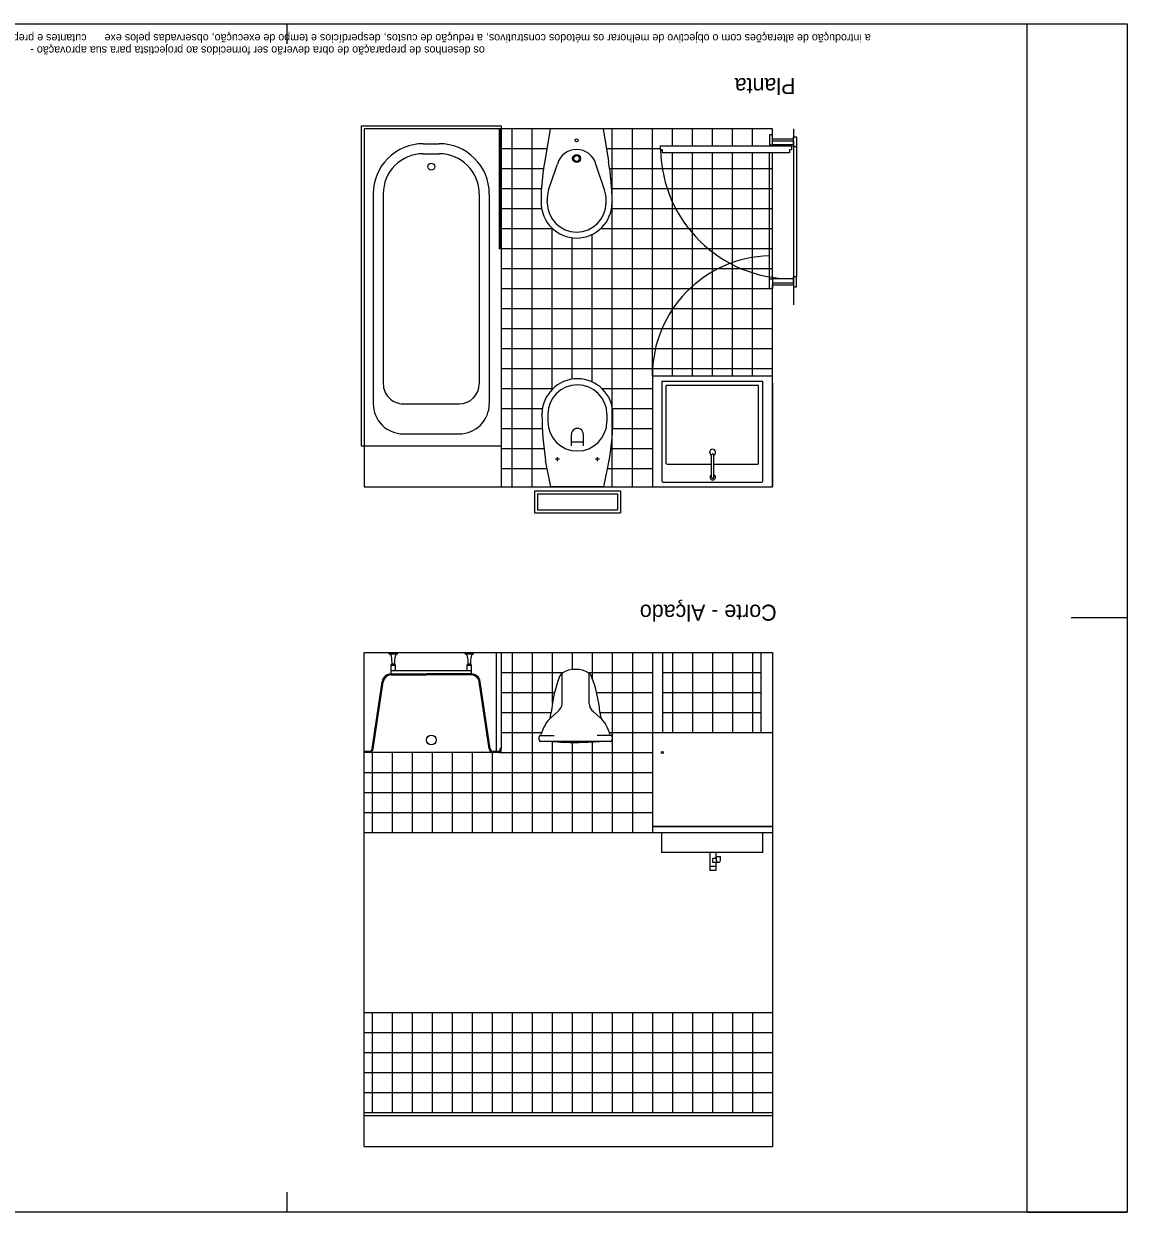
# Model space of a CAD drawing. Extents: x 1279.2 to 1290.8, y -284.8 to -278.9.
# Drawn here: x 1285.25 to 1290.76, y -284.82 to -278.88 of the extents above; entities that cross this region are included whole.
import ezdxf

# ---------------------------------------------------------------- set-up
doc = ezdxf.new("R2010")
doc.units = 0
for name, color, linetype in [('Level 1', 7, 'Continuous'), ('Level 10', 7, 'Continuous'), ('Level 11', 7, 'Continuous'), ('Level 13', 7, 'Continuous'), ('Level 18', 7, 'Continuous'), ('Level 2', 7, 'Continuous'), ('Level 36', 7, 'Continuous'), ('Level 4', 7, 'Continuous'), ('Level 60', 7, 'Continuous'), ('Level 62', 7, 'Continuous')]:
    doc.layers.add(name, color=color, linetype=linetype)

msp = doc.modelspace()

# ---------------------------------------------------------------- linework, layer by layer
at = {"layer": 'Level 1'}
for p, q in [((1288.9899, -279.4078), (1286.9499, -279.4078)), ((1286.9499, -279.4078), (1286.9499, -281.1978)), ((1288.9899, -279.4578), (1288.9899, -279.4078)), ((1289.0949, -279.4078), (1289.0949, -279.4578)), ((1288.9899, -279.4578), (1289.0949, -279.4578)), ((1288.9899, -281.1978), (1288.9899, -280.1878)), ((1288.9899, -280.1878), (1289.0949, -280.1878)), ((1289.0949, -280.1878), (1289.0949, -280.2878)), ((1286.9499, -281.1978), (1288.9899, -281.1978)), ((1286.9499, -282.0252), (1288.9899, -282.0252)), ((1286.9499, -284.4952), (1286.9499, -282.0252)), ((1287.6099, -282.0252), (1287.6099, -282.5202)), ((1287.6349, -282.0252), (1287.6349, -282.5052)), ((1288.9899, -282.0252), (1288.9899, -284.4952)), ((1287.6349, -282.5052), (1287.6299, -282.5052)), ((1287.6299, -282.5052), (1287.6299, -282.5102)), ((1287.6199, -282.5202), (1287.6099, -282.5202)), ((1286.9499, -284.3252), (1287.6349, -284.3252)), ((1286.9499, -284.3402), (1288.9899, -284.3402)), ((1287.6349, -284.3252), (1288.9899, -284.3252)), ((1286.9499, -284.4952), (1288.9899, -284.4952))]:
    msp.add_line(p, q, dxfattribs=at)
msp.add_arc((1287.6199, -282.5102), 0.01, 270, 0, dxfattribs=at)
at = {"layer": 'Level 10'}
for p, q in [((1287.6899, -281.1978), (1287.6899, -279.4078)), ((1287.7899, -281.1978), (1287.7899, -279.4078)), ((1288.1899, -281.1978), (1288.1899, -279.4078)), ((1288.2899, -281.1978), (1288.2899, -279.4078)), ((1288.3899, -280.6428), (1288.3899, -279.4078)), ((1288.4899, -279.4928), (1288.4899, -279.4078)), ((1288.5899, -279.4928), (1288.5899, -279.4078)), ((1288.6899, -279.4928), (1288.6899, -279.4078)), ((1288.7899, -279.4928), (1288.7899, -279.4078)), ((1288.8899, -279.4928), (1288.8899, -279.4078)), ((1287.8625, -279.5078), (1287.6349, -279.5078)), ((1288.4306, -279.5078), (1288.16, -279.5078)), ((1288.4899, -280.6428), (1288.4899, -279.5278)), ((1288.5899, -280.6428), (1288.5899, -279.5278)), ((1288.6899, -280.6428), (1288.6899, -279.5278)), ((1288.7899, -280.6428), (1288.7899, -279.5278)), ((1288.8899, -280.6428), (1288.8899, -279.5278)), ((1288.9899, -280.1578), (1288.9899, -279.5278)), ((1289.0949, -279.4978), (1289.0949, -280.1478)), ((1287.846, -279.6078), (1287.6349, -279.6078)), ((1288.9899, -279.6078), (1288.1765, -279.6078)), ((1287.8357, -279.7078), (1287.6349, -279.7078)), ((1288.9899, -279.7078), (1288.1869, -279.7078)), ((1287.8365, -279.8078), (1287.6349, -279.8078)), ((1288.9899, -279.8078), (1288.186, -279.8078)), ((1287.8918, -279.9078), (1287.6349, -279.9078)), ((1287.8899, -280.7097), (1287.8899, -279.9061)), ((1288.0899, -280.6738), (1288.0899, -279.9357)), ((1288.9899, -279.9078), (1288.1307, -279.9078)), ((1288.9899, -280.0078), (1287.6349, -280.0078)), ((1287.9899, -280.6582), (1287.9899, -279.9529)), ((1288.9899, -280.1078), (1287.6349, -280.1078)), ((1288.9899, -280.2078), (1287.6349, -280.2078)), ((1288.9899, -280.3078), (1287.6349, -280.3078)), ((1288.9899, -280.4078), (1287.6349, -280.4078)), ((1288.9899, -280.5078), (1287.6349, -280.5078)), ((1288.9899, -280.6078), (1287.6349, -280.6078)), ((1287.8918, -280.7078), (1287.6349, -280.7078)), ((1288.3899, -280.7078), (1288.1395, -280.7078)), ((1287.8402, -280.8078), (1287.6349, -280.8078)), ((1288.3899, -280.8078), (1288.191, -280.8078)), ((1287.8398, -280.9078), (1287.6349, -280.9078)), ((1288.3899, -280.9078), (1288.1914, -280.9078)), ((1287.8484, -281.0078), (1287.6349, -281.0078)), ((1288.3899, -281.0078), (1288.1828, -281.0078)), ((1287.8652, -281.1078), (1287.6349, -281.1078)), ((1288.3899, -281.1078), (1288.1661, -281.1078)), ((1287.6899, -282.0252), (1287.6899, -282.9252)), ((1287.7899, -282.0252), (1287.7899, -282.9252)), ((1287.8899, -282.0252), (1287.8899, -282.2794)), ((1287.9899, -282.0252), (1287.9899, -282.111)), ((1288.0899, -282.0252), (1288.0899, -282.1572)), ((1288.1899, -282.0252), (1288.1899, -282.9252)), ((1288.2899, -282.0252), (1288.2899, -282.9252)), ((1288.4899, -282.0252), (1288.4899, -282.4252)), ((1288.5899, -282.0252), (1288.5899, -282.4252)), ((1288.6899, -282.0252), (1288.6899, -282.4252)), ((1288.7899, -282.0252), (1288.7899, -282.4252)), ((1288.8899, -282.0252), (1288.8899, -282.4252)), ((1288.9899, -282.0252), (1288.9899, -282.4252)), ((1287.6349, -282.1252), (1287.9447, -282.1252)), ((1288.0674, -282.1252), (1288.3899, -282.1252)), ((1288.4399, -282.1252), (1288.9329, -282.1252)), ((1287.6349, -282.2252), (1287.901, -282.2252)), ((1288.1111, -282.2252), (1288.3899, -282.2252)), ((1288.4399, -282.2252), (1288.9329, -282.2252)), ((1287.6349, -282.3252), (1287.8843, -282.3252)), ((1288.1278, -282.3252), (1288.3899, -282.3252)), ((1288.4399, -282.3252), (1288.9329, -282.3252)), ((1287.6349, -282.4252), (1287.7399, -282.4252)), ((1287.7399, -282.4252), (1287.8373, -282.4252)), ((1288.1748, -282.4252), (1288.3919, -282.4252)), ((1287.8899, -282.4695), (1287.8899, -282.9252)), ((1287.9899, -282.4729), (1287.9899, -282.9252)), ((1288.0899, -282.4751), (1288.0899, -282.9252)), ((1286.9899, -282.5252), (1286.9899, -282.9252)), ((1287.0899, -282.5252), (1287.0899, -282.9252)), ((1287.1899, -282.5252), (1287.1899, -282.9252)), ((1287.2899, -282.5252), (1287.2899, -282.9252)), ((1287.3899, -282.5252), (1287.3899, -282.9252)), ((1287.4899, -282.5252), (1287.4899, -282.9252)), ((1287.5899, -282.5252), (1287.5899, -282.9252)), ((1287.6249, -282.5252), (1287.7399, -282.5252)), ((1287.7399, -282.5252), (1288.3899, -282.5252)), ((1286.9499, -282.6252), (1287.7399, -282.6252)), ((1287.7399, -282.6252), (1288.3899, -282.6252)), ((1286.9499, -282.7252), (1288.3899, -282.7252)), ((1286.9499, -282.8252), (1288.3899, -282.8252)), ((1286.9899, -283.8252), (1286.9899, -284.3252)), ((1287.0899, -283.8252), (1287.0899, -284.3252)), ((1287.1899, -283.8252), (1287.1899, -284.3252)), ((1287.2899, -283.8252), (1287.2899, -284.3252)), ((1287.3899, -283.8252), (1287.3899, -284.3252)), ((1287.4899, -283.8252), (1287.4899, -284.3252)), ((1287.5899, -283.8252), (1287.5899, -284.3252)), ((1287.6899, -283.8252), (1287.6899, -284.3252)), ((1287.7899, -283.8252), (1287.7899, -284.3252)), ((1287.8899, -283.8252), (1287.8899, -284.3252)), ((1287.9899, -283.8252), (1287.9899, -284.3252)), ((1288.0899, -283.8252), (1288.0899, -284.3252)), ((1288.1899, -283.8252), (1288.1899, -284.3252)), ((1288.2899, -283.8252), (1288.2899, -284.3252)), ((1288.3899, -283.8252), (1288.3899, -284.3252)), ((1288.4899, -283.8252), (1288.4899, -284.3252)), ((1288.5899, -283.8252), (1288.5899, -284.3252)), ((1288.6899, -283.8252), (1288.6899, -284.3252)), ((1288.7899, -283.8252), (1288.7899, -284.3252)), ((1288.8899, -283.8252), (1288.8899, -284.3252)), ((1288.9899, -284.1252), (1288.9899, -284.4952)), ((1286.9499, -284.2252), (1287.6349, -284.2252)), ((1287.6349, -284.2252), (1288.9899, -284.2252))]:
    msp.add_line(p, q, dxfattribs=at)
at = {"layer": 'Level 11'}
for p, q in [((1286.9349, -279.3928), (1286.9349, -280.9928)), ((1286.9349, -279.3928), (1287.6349, -279.3928)), ((1287.6349, -279.3928), (1287.6349, -280.9928)), ((1287.8789, -279.4078), (1287.8523, -279.5699)), ((1288.1436, -279.4078), (1287.8789, -279.4078)), ((1288.1436, -279.4078), (1288.1702, -279.5699)), ((1287.2449, -279.4828), (1287.3249, -279.4828)), ((1287.2449, -279.5328), (1287.3249, -279.5328)), ((1287.8714, -279.7136), (1287.9151, -279.5844)), ((1288.1511, -279.7136), (1288.1074, -279.5844)), ((1286.9949, -279.7328), (1286.9949, -280.7828)), ((1287.0449, -279.7328), (1287.0449, -280.6828)), ((1287.5249, -279.7328), (1287.5249, -280.6828)), ((1287.5749, -279.7328), (1287.5749, -280.7828)), ((1287.8338, -279.7732), (1287.8338, -279.7769)), ((1287.8638, -279.7766), (1287.8638, -279.7685)), ((1288.1588, -279.7766), (1288.1588, -279.7685)), ((1288.1888, -279.7732), (1288.1888, -279.7769)), ((1288.4377, -280.6708), (1288.4377, -281.1699)), ((1288.9421, -280.6708), (1288.4377, -280.6708)), ((1288.4588, -281.0803), (1288.4588, -280.6918)), ((1288.921, -280.6918), (1288.4588, -280.6918)), ((1288.921, -281.0804), (1288.921, -280.6918)), ((1288.9421, -281.1699), (1288.9421, -280.6708)), ((1287.1449, -280.7828), (1287.4249, -280.7828)), ((1287.8381, -280.8384), (1287.8381, -280.8347)), ((1287.8681, -280.835), (1287.8681, -280.8711)), ((1288.1631, -280.835), (1288.1631, -280.8711)), ((1288.1931, -280.8384), (1288.1931, -280.8347)), ((1287.1449, -280.9328), (1287.4249, -280.9328)), ((1287.9856, -280.993), (1287.9856, -280.9357)), ((1288.0456, -280.993), (1288.0456, -280.9358)), ((1286.9349, -280.9928), (1287.6349, -280.9928)), ((1288.0456, -280.9753), (1287.9856, -280.9753)), ((1287.8833, -281.1978), (1287.8567, -281.0655)), ((1287.9256, -281.0593), (1287.9056, -281.0593)), ((1287.9156, -281.0693), (1287.9156, -281.0493)), ((1288.1256, -281.0593), (1288.1056, -281.0593)), ((1288.1156, -281.0693), (1288.1156, -281.0493)), ((1288.148, -281.1978), (1288.1746, -281.0655)), ((1288.686, -281.1492), (1288.686, -281.0396)), ((1288.6972, -281.1492), (1288.6972, -281.0396)), ((1288.4632, -281.0847), (1288.686, -281.0847)), ((1288.6972, -281.0847), (1288.9166, -281.0847)), ((1288.148, -281.1978), (1287.8833, -281.1978)), ((1288.4421, -281.1743), (1288.9377, -281.1743)), ((1287.8006, -281.2178), (1287.8006, -281.3278)), ((1287.8006, -281.2178), (1288.2306, -281.2178)), ((1287.8156, -281.2328), (1288.2156, -281.2328)), ((1287.8156, -281.2328), (1287.8156, -281.3128)), ((1288.2156, -281.2328), (1288.2156, -281.3128)), ((1288.2306, -281.2178), (1288.2306, -281.3278)), ((1287.8156, -281.3128), (1288.2156, -281.3128)), ((1287.8006, -281.3278), (1288.2306, -281.3278)), ((1287.0742, -282.0251), (1287.1155, -282.0251)), ((1287.0742, -282.0318), (1287.0742, -282.0251)), ((1287.1155, -282.0318), (1287.1155, -282.0251)), ((1287.4544, -282.0251), (1287.4957, -282.0251)), ((1287.4544, -282.0318), (1287.4544, -282.0251)), ((1287.4957, -282.0318), (1287.4957, -282.0251)), ((1287.0742, -282.0318), (1287.1155, -282.0318)), ((1287.0843, -282.0887), (1287.0892, -282.0827)), ((1287.0843, -282.0887), (1287.1053, -282.0887)), ((1287.0843, -282.1151), (1287.0843, -282.0887)), ((1287.0892, -282.0827), (1287.1004, -282.0827)), ((1287.1053, -282.0887), (1287.1004, -282.0827)), ((1287.1053, -282.1151), (1287.1053, -282.0887)), ((1287.4544, -282.0318), (1287.4957, -282.0318)), ((1287.4645, -282.0887), (1287.4694, -282.0827)), ((1287.4645, -282.0887), (1287.4855, -282.0887)), ((1287.4645, -282.1151), (1287.4645, -282.0887)), ((1287.4694, -282.0827), (1287.4806, -282.0827)), ((1287.4855, -282.0887), (1287.4806, -282.0827)), ((1287.4855, -282.1332), (1287.4855, -282.0887)), ((1287.0843, -282.1379), (1287.0843, -282.1151)), ((1287.0843, -282.1151), (1287.4855, -282.1151)), ((1287.0843, -282.1332), (1287.2606, -282.1332)), ((1287.0843, -282.1382), (1287.2606, -282.1382)), ((1287.3091, -282.1332), (1287.2606, -282.1332)), ((1287.3091, -282.1382), (1287.2606, -282.1382)), ((1287.4855, -282.1332), (1287.3091, -282.1332)), ((1287.4855, -282.1382), (1287.3091, -282.1382)), ((1287.9385, -282.2801), (1287.9385, -282.1287)), ((1288.0735, -282.2801), (1288.0735, -282.1287)), ((1286.9899, -282.5061), (1287.0398, -282.1716)), ((1286.9948, -282.5069), (1287.0447, -282.1723)), ((1287.5748, -282.5069), (1287.525, -282.1723)), ((1287.5799, -282.5074), (1287.53, -282.1716)), ((1287.88, -282.3541), (1287.8843, -282.3254)), ((1287.8843, -282.3501), (1287.9171, -282.3199)), ((1288.1277, -282.3501), (1288.0949, -282.3199)), ((1288.1277, -282.3254), (1288.132, -282.3541)), ((1287.8293, -282.4398), (1287.8986, -282.4398)), ((1288.1827, -282.4398), (1288.1134, -282.4398)), ((1287.6349, -282.5052), (1287.6299, -282.5052)), ((1287.6299, -282.5152), (1287.6299, -282.5052)), ((1287.6349, -282.5152), (1287.6349, -282.5052)), ((1287.8235, -282.4621), (1287.8235, -282.4475)), ((1288.1885, -282.4475), (1288.1885, -282.4621)), ((1286.9749, -282.5202), (1286.9499, -282.5202)), ((1286.9749, -282.5252), (1286.9499, -282.5252)), ((1287.5949, -282.5252), (1286.9749, -282.5252)), ((1287.6249, -282.5252), (1287.5947, -282.5252)), ((1287.6249, -282.5202), (1287.5948, -282.5202)), ((1288.4377, -283.0252), (1288.4377, -282.9252)), ((1288.9421, -283.0252), (1288.9421, -282.9252)), ((1288.6772, -283.0252), (1288.6772, -283.1152)), ((1288.7072, -283.0252), (1288.7072, -283.0552)), ((1288.6772, -283.0752), (1288.6772, -283.1152)), ((1288.7072, -283.0952), (1288.6772, -283.0952)), ((1288.7072, -283.0752), (1288.7072, -283.1152)), ((1288.7098, -283.0652), (1288.7098, -283.0452)), ((1288.7098, -283.0452), (1288.7298, -283.0452)), ((1288.7298, -283.0652), (1288.7298, -283.0452)), ((1288.7072, -283.1152), (1288.6772, -283.1152))]:
    msp.add_line(p, q, dxfattribs=at)
msp.add_lwpolyline([(1288.1805, -282.4701), (1288.0035, -282.4701), (1287.8315, -282.4701)], dxfattribs=at)
for centre, radius in [((1288.0113, -279.4658), 0.00766), ((1287.2849, -279.5973), 0.0173), ((1288.0113, -279.5567), 0.02), ((1288.0113, -279.5567), 0.0146), ((1287.2849, -282.4632), 0.0242)]:
    msp.add_circle(centre, radius, dxfattribs=at)
for centre, radius, start, end in [((1287.2449, -279.7328), 0.25, 89.99986, 179.99993), ((1287.2449, -279.7328), 0.2, 89.99997, 180.00001), ((1287.3249, -279.7328), 0.25, 359.99999, 90.0001), ((1287.3249, -279.7328), 0.2, 359.99997, 90.00002), ((1288.0113, -279.6118), 0.1, 15.80471, 164.06834), ((1288.0638, -279.7685), 0.2, 164.06814, 179.99835), ((1287.9588, -279.7685), 0.2, 359.99944, 15.93072), ((1288.0113, -279.7766), 0.1775, 180.00014, 359.99982), ((1288.0113, -279.7766), 0.1475, 180.00014, 359.99982), ((1288.0156, -280.835), 0.1775, 0.00023, 179.99991), ((1287.1449, -280.6828), 0.1, 179.99997, 270.00005), ((1287.4249, -280.6828), 0.1, 270.00014, 359.99987), ((1288.0156, -280.835), 0.1475, 0.00023, 179.99991), ((1287.1449, -280.7828), 0.15, 179.99996, 269.99999), ((1287.4249, -280.7828), 0.15, 269.9999, 0.00017), ((1289.2381, -280.8384), 1.4, 179.99994, 189.33448), ((1286.7931, -280.8384), 1.4, 350.66561, 0.00015), ((1288.0156, -280.8711), 0.1475, 180.00018, 359.99986), ((1288.0156, -280.936), 0.03, 359.99953, 180.00125), ((1288.6912, -281.0252), 0.015, 293.63069, 249.28331), ((1288.4632, -281.0803), 0.00438, 180, 270), ((1288.6916, -281.0391), 0.00566, 354.01756, 185.9962), ((1288.9166, -281.0804), 0.00438, 270, 0), ((1288.692, -281.1497), 0.0135, 116.71993, 67.39087), ((1288.4421, -281.1699), 0.00438, 180, 270), ((1288.6916, -281.1497), 0.00566, 174.0038, 5.98244), ((1288.9377, -281.1699), 0.00438, 270, 0), ((1287.0677, -282.0489), 0.0182, 10.7191, 69.4894), ((1286.8894, -282.0827), 0.1997, 0, 10.7194), ((1287.3001, -282.0827), 0.1997, 169.2807, 180), ((1287.1218, -282.0489), 0.0182, 110.5111, 169.2809), ((1287.4479, -282.0489), 0.0182, 10.7191, 69.4894), ((1287.2697, -282.0827), 0.1997, 0, 10.7194), ((1287.6803, -282.0827), 0.1997, 169.2807, 180), ((1287.502, -282.0489), 0.0182, 110.5111, 169.2809), ((1287.0843, -282.1782), 0.045, 89.99967, 171.51795), ((1287.0843, -282.1782), 0.04, 90.00021, 171.51768), ((1287.4855, -282.1782), 0.045, 8.45973, 90.00001), ((1287.4855, -282.1782), 0.04, 8.46004, 90.0002), ((1288.508, -282.3775), 0.6258, 157.87828, 175.22161), ((1287.959, -282.1553), 0.0336, 127.37509, 156.36146), ((1288.006, -282.2411), 0.1312, 59.05228, 120.94772), ((1288.0531, -282.1553), 0.0336, 23.63854, 52.62491), ((1287.5041, -282.3775), 0.6258, 4.77839, 22.12172), ((1287.887, -282.278), 0.0516, 305.66936, 357.68937), ((1288.1251, -282.278), 0.0516, 182.31063, 234.33064), ((1287.998, -282.4734), 0.1678, 132.66339, 166.38286), ((1288.0141, -282.4734), 0.1678, 13.61714, 47.33661), ((1287.8316, -282.4474), 0.008, 106.01353, 180), ((1287.8272, -282.432), 0.008, 286.01353, 346.38286), ((1288.1849, -282.432), 0.008, 193.61714, 253.98647), ((1288.1805, -282.4474), 0.008, 0, 73.98647), ((1287.8316, -282.462), 0.008, 180, 270), ((1288.0126, -280.9154), 1.5598, 265.33547, 269.85152), ((1287.9985, -280.8995), 1.5757, 270.36771, 274.65314), ((1288.1805, -282.462), 0.008, 270, 0), ((1286.9749, -282.5052), 0.015, 269.99948, 355.23623), ((1286.9749, -282.5052), 0.02, 269.99948, 355.23623), ((1287.5947, -282.5052), 0.02, 184.76282, 270.00041), ((1287.5948, -282.5052), 0.015, 188.45921, 269.99916), ((1287.6249, -282.5152), 0.005, 269.99979, 359.9959), ((1287.6249, -282.5152), 0.01, 269.99878, 0.00082), ((1288.7198, -283.0652), 0.01, 180, 0)]:
    msp.add_arc(centre, radius, start, end, dxfattribs=at)
for centre, major_axis, start_param, end_param in [((1289.2338, -279.7732), (-1.4, 0), 6.120269, 6.283187), ((1286.7888, -279.7732), (1.4, 0), 6.283183, 6.446102)]:
    msp.add_ellipse(centre, major_axis=major_axis, ratio=0.895428, start_param=start_param, end_param=end_param, dxfattribs=at)
at = {"layer": 'Level 13'}
for p, q in [((1288.9749, -279.4378), (1288.9749, -279.4878)), ((1288.9899, -279.4378), (1288.9749, -279.4378)), ((1288.9899, -279.4878), (1288.9899, -279.4378)), ((1288.9899, -279.4678), (1289.0949, -279.4678)), ((1288.9899, -279.4878), (1288.9899, -279.4678)), ((1289.0949, -279.4978), (1289.0949, -279.4478)), ((1289.0949, -279.4478), (1289.1099, -279.4478)), ((1289.0949, -279.4678), (1289.0949, -279.4978)), ((1289.1099, -279.4478), (1289.1099, -279.4978)), ((1288.4306, -279.4928), (1289.0856, -279.4928)), ((1288.4306, -279.5128), (1288.4306, -279.4928)), ((1288.4406, -279.5128), (1288.4309, -279.5128)), ((1288.4406, -279.5278), (1288.4406, -279.5128)), ((1289.0756, -279.5278), (1288.4406, -279.5278)), ((1288.9749, -279.4878), (1288.9899, -279.4878)), ((1289.0949, -279.4878), (1288.9899, -279.4878)), ((1289.0756, -279.5128), (1289.0756, -279.5278)), ((1289.0856, -279.5128), (1289.0756, -279.5128)), ((1289.0856, -279.4928), (1289.0856, -279.5128)), ((1289.1099, -279.4978), (1289.0949, -279.4978)), ((1288.9749, -280.2078), (1288.9749, -280.1578)), ((1288.9749, -280.1578), (1288.9899, -280.1578)), ((1289.0949, -280.1578), (1288.9899, -280.1578)), ((1288.9899, -280.1578), (1288.9899, -280.1778)), ((1288.9899, -280.1578), (1288.9899, -280.2078)), ((1288.9899, -280.1778), (1289.0949, -280.1778)), ((1289.0949, -280.1778), (1289.0949, -280.1478)), ((1289.1099, -280.1478), (1289.0949, -280.1478)), ((1289.0949, -280.1478), (1289.0949, -280.1978)), ((1289.1099, -280.1978), (1289.1099, -280.1478)), ((1288.9899, -280.2078), (1288.9749, -280.2078)), ((1289.0949, -280.1978), (1289.1099, -280.1978)), ((1288.3899, -282.0252), (1288.3899, -282.9252)), ((1288.4399, -282.0252), (1288.4399, -282.4252)), ((1288.9329, -282.0252), (1288.9329, -282.4252)), ((1288.3899, -282.4252), (1288.9899, -282.4252)), ((1288.3899, -282.8932), (1288.9899, -282.8932)), ((1288.3899, -282.8952), (1288.9899, -282.8952)), ((1288.3899, -282.9252), (1288.9899, -282.9252)), ((1288.9421, -283.0252), (1288.4377, -283.0252))]:
    msp.add_line(p, q, dxfattribs=at)
msp.add_circle((1288.4399, -282.5252), 0.005, dxfattribs=at)
at = {"layer": 'Level 18'}
for p, q in [((1286.9499, -283.9252), (1288.9899, -283.9252)), ((1286.9499, -284.0252), (1288.9899, -284.0252)), ((1286.9499, -284.1252), (1288.9899, -284.1252))]:
    msp.add_line(p, q, dxfattribs=at)
at = {"layer": 'Level 2'}
for p, q in [((1288.3899, -280.6428), (1288.3899, -281.1978)), ((1288.3899, -280.6428), (1288.9899, -280.6428)), ((1288.9899, -280.6778), (1288.9899, -281.1978)), ((1287.6349, -280.9928), (1287.6349, -281.1978)), ((1286.9499, -282.9252), (1287.7399, -282.9252)), ((1287.7399, -282.9252), (1288.3919, -282.9252)), ((1288.6922, -283.0752), (1288.6922, -283.0552)), ((1288.7098, -283.0552), (1288.6922, -283.0552)), ((1288.7198, -283.0752), (1288.6922, -283.0752)), ((1286.9499, -283.8252), (1288.9899, -283.8252))]:
    msp.add_line(p, q, dxfattribs=at)
at = {"layer": 'Level 36'}
for p, q in [((1287.6249, -279.4078), (1287.6249, -280.0078)), ((1287.6299, -279.4078), (1287.6299, -280.0078)), ((1287.6299, -280.0078), (1287.6249, -280.0078))]:
    msp.add_line(p, q, dxfattribs=at)
at = {"layer": 'Level 4'}
for p, q in [((1288.9749, -280.1578), (1288.9749, -279.5278)), ((1289.1099, -279.4978), (1289.1099, -280.1478))]:
    msp.add_line(p, q, dxfattribs=at)
msp.add_arc((1288.9899, -280.6428), 0.6, 91.43254, 180, dxfattribs=at)
msp.add_ellipse((1289.0856, -279.4992), major_axis=(0, 0.6586), ratio=0.994276, start_param=1.591512, end_param=3.141593, dxfattribs=at)
at = {"layer": 'Level 62'}
for p, q in [((1286.564, -278.9833), (1286.564, -278.8833)), ((1290.2636, -284.8233), (1290.2636, -278.8833)), ((1290.7636, -281.8533), (1290.4836, -281.8533)), ((1286.5632, -284.7233), (1286.5632, -284.8233)), ((1290.2636, -284.8233), (1290.7636, -284.8233))]:
    msp.add_line(p, q, dxfattribs=at)
msp.add_lwpolyline([(1290.7636, -278.8833), (1290.7636, -284.8233), (1279.164, -284.8233), (1279.164, -278.8833)], close=True, dxfattribs=at)

# ---------------------------------------------------------------- texts
at = {"layer": 'Level 60'}
for s, p in [('Planta', (1289.1048, -279.155)), ('Corte - Alçado', (1289.0112, -281.7866))]:
    msp.add_text(s, height=0.08, rotation=180.00001, dxfattribs=at).set_placement(p)
at = {"layer": 'Level 62'}
for s, height, p in [('cutantes e preparadores da obra deverão ser sugeridas. não poderão no entanto ser implementadas sem o consentimento expresso dos responsáveis pela arquitectura', 0.0399996, (1285.5618, -278.9353)), ('a introdução de alterações com o objectivo de melhorar os métodos construtivos, a redução de custos, desperdícios e tempo de execução, observadas pelos exe', 0.0399996, (1289.4816, -278.9353)), ('os desenhos de preparação de obra deverão ser fornecidos ao projectista para sua aprovação -', 0.04, (1287.5526, -278.9963))]:
    msp.add_text(s, height=height, rotation=180, dxfattribs=at).set_placement(p)

doc.saveas('drawing.dxf')
